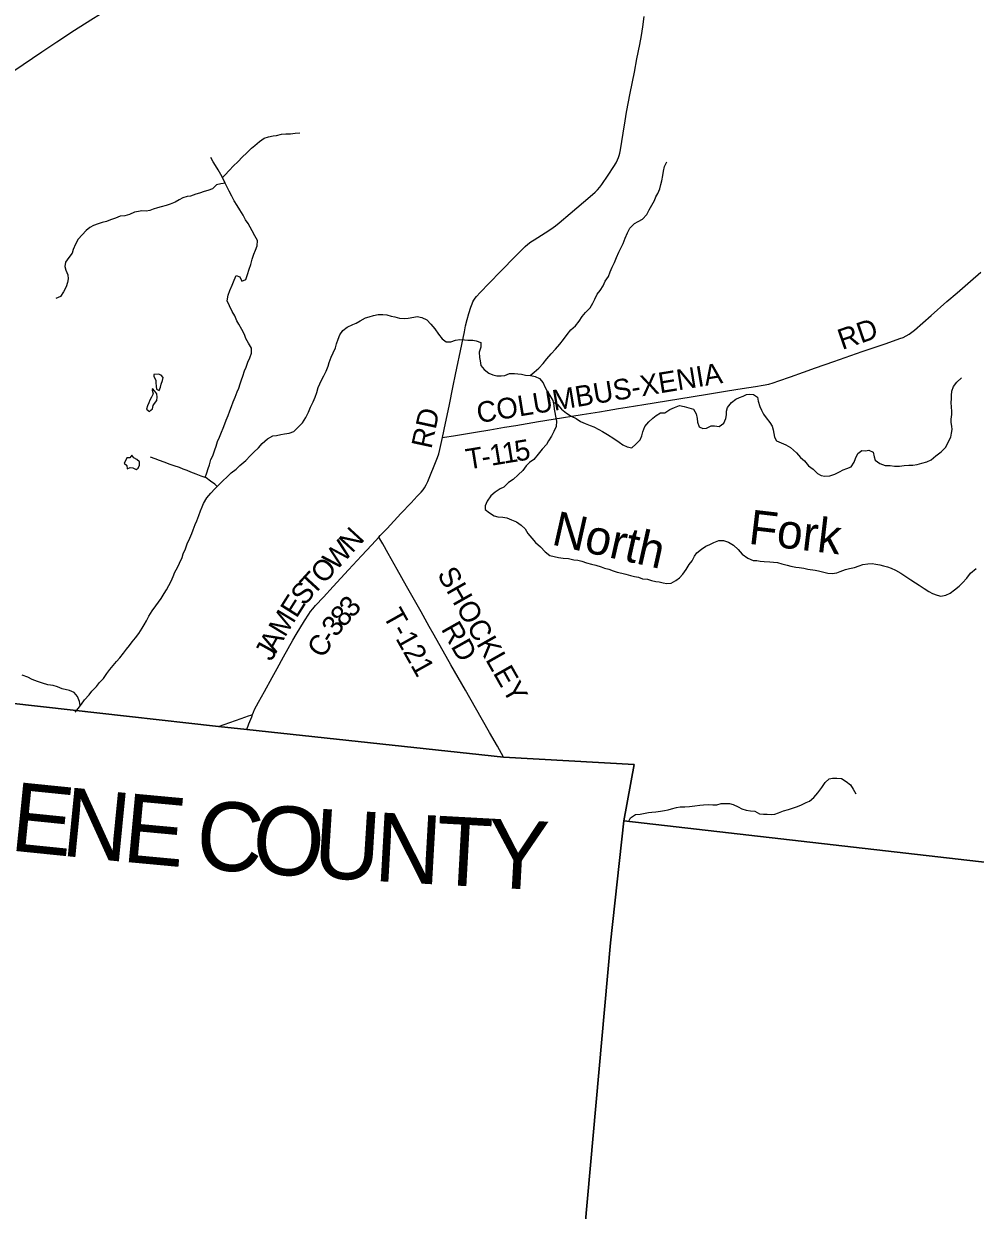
# Model space of a CAD drawing. Extents: x 1410790 to 1770854, y 566777 to 831614.
# Drawn here: x 1637179 to 1651013, y 642079 to 659329 of the extents above; entities that cross this region are included whole.
import ezdxf

# ---------------------------------------------------------------- set-up
doc = ezdxf.new("R2010")
doc.units = 0
for name, color, linetype in [('GM_X_Adjacent_County', 7, 'Continuous'), ('GM_X_Adjacent_County_Text', 7, 'Continuous'), ('GM_X_County', 7, 'Continuous'), ('GM_X_County_Road', 7, 'Continuous'), ('GM_X_County_Road_Text', 7, 'Continuous'), ('GM_X_Minor_Lake', 7, 'Continuous'), ('GM_X_Minor_River', 7, 'Continuous'), ('GM_X_Minor_River_Text', 7, 'Continuous'), ('GM_X_Township', 7, 'Continuous'), ('GM_X_Township_Road', 7, 'Continuous'), ('GM_X_Township_Road_Text', 7, 'Continuous')]:
    doc.layers.add(name, color=color, linetype=linetype)

msp = doc.modelspace()

# ---------------------------------------------------------------- linework, layer by layer
at = {"layer": 'GM_X_Adjacent_County'}
for points in [[(1671974, 683181), (1671693, 682151), (1669822, 675181), (1669783, 675026), (1667943, 667921), (1667581, 666498), (1666885, 663874), (1666084, 660564), (1663561, 650929), (1663296, 649933), (1662403, 645855), (1656287, 646528), (1652288, 647008), (1645905, 647740), (1645710, 645966), (1645124, 639449)], [(1645124, 639449), (1645710, 645966), (1645905, 647740), (1646054, 648559), (1644155, 648666), (1640422, 649068), (1640009, 649114), (1636122, 649546)]]:
    msp.add_lwpolyline(points, dxfattribs=at)
at = {"layer": 'GM_X_County'}
msp.add_lwpolyline([(1671974, 683181), (1671693, 682151), (1669822, 675181), (1669783, 675026), (1667943, 667921), (1667581, 666498), (1666885, 663874), (1666084, 660564), (1663561, 650929), (1663296, 649933), (1662403, 645855), (1656287, 646528), (1652288, 647008), (1645905, 647740), (1646054, 648559), (1644155, 648666), (1640422, 649068), (1640009, 649114), (1636122, 649546)], dxfattribs=at)
at = {"layer": 'GM_X_County_Road'}
for points in [[(1636750, 658448), (1636844, 658513), (1636979, 658605), (1637169, 658736), (1637441, 658919), (1637659, 659066), (1637919, 659237), (1638155, 659386), (1638294, 659472), (1638461, 659576), (1638767, 659768), (1638906, 659855), (1639087, 659968), (1639310, 660107), (1639478, 660210), (1639869, 660451), (1640134, 660615), (1640329, 660736), (1640524, 660857), (1640691, 660961), (1640872, 661072), (1641016, 661164)], [(1643266, 653314), (1643309, 653523), (1643363, 653771), (1643424, 654064), (1643458, 654228), (1643548, 654667), (1643585, 654850), (1643604, 654939), (1643627, 655027), (1643652, 655118), (1643679, 655208), (1643697, 655257), (1643709, 655284), (1643725, 655311), (1643742, 655338), (1643764, 655365), (1643817, 655423), (1643947, 655557), (1644116, 655733), (1644328, 655951), (1644424, 656047), (1644470, 656091), (1644509, 656124), (1644552, 656156), (1644602, 656189), (1644762, 656289), (1644844, 656343), (1644911, 656391), (1644962, 656432), (1645124, 656571), (1645412, 656815), (1645486, 656880), (1645521, 656915), (1645553, 656953), (1645583, 656993), (1645674, 657129), (1645756, 657252), (1645790, 657308), (1645813, 657352), (1645826, 657383), (1645837, 657414), (1645845, 657446), (1645855, 657495), (1645894, 657738), (1645923, 657916), (1645944, 658045), (1645996, 658319), (1646057, 658625), (1646094, 658818), (1646136, 659027), (1646160, 659156), (1646180, 659286), (1646199, 659433)], [(1642341, 651865), (1642363, 651888), (1642461, 651990), (1642661, 652207), (1642810, 652363), (1642901, 652459), (1642955, 652519), (1642986, 652555), (1643005, 652582), (1643030, 652625), (1643053, 652672), (1643084, 652747), (1643156, 652925), (1643194, 653025), (1643212, 653078), (1643228, 653140), (1643266, 653314)], [(1640506, 649287), (1640519, 649320), (1640536, 649359), (1640593, 649468), (1640679, 649622), (1640791, 649825), (1640863, 649954), (1640957, 650125), (1641092, 650366), (1641141, 650451), (1641261, 650647), (1641322, 650743), (1641350, 650784), (1641380, 650822), (1641423, 650872), (1641535, 650991), (1641680, 651148), (1641903, 651389), (1642092, 651594), (1642239, 651755), (1642341, 651865)], [(1640009, 649114), (1640340, 649229), (1640448, 649266), (1640480, 649278), (1640506, 649287)], [(1640422, 649068), (1640454, 649153), (1640493, 649255), (1640506, 649287)]]:
    msp.add_lwpolyline(points, dxfattribs=at)
at = {"layer": 'GM_X_Minor_Lake'}
for points in [[(1639157, 654021), (1639166, 654045), (1639176, 654091), (1639197, 654141), (1639205, 654185), (1639176, 654221), (1639136, 654235), (1639070, 654228)], [(1639070, 654228), (1639072, 654200), (1639101, 654148), (1639102, 654107), (1639104, 654059), (1639107, 654015), (1639147, 653997), (1639157, 654021)], [(1639051, 654024), (1639044, 654003), (1639059, 653950), (1639036, 653898), (1639014, 653858), (1638999, 653816), (1638977, 653772), (1638966, 653724), (1639008, 653692), (1639028, 653711)], [(1639028, 653711), (1639049, 653731), (1639063, 653777), (1639081, 653809), (1639112, 653853), (1639120, 653899), (1639113, 653947), (1639083, 653989), (1639051, 654024)], [(1638694, 653019), (1638679, 653020), (1638660, 652976), (1638640, 652942), (1638676, 652908), (1638685, 652856), (1638727, 652877), (1638767, 652871), (1638813, 652850)], [(1638813, 652850), (1638842, 652870), (1638864, 652910), (1638861, 652958), (1638825, 652996), (1638779, 653017), (1638753, 653057), (1638723, 653017), (1638694, 653019)]]:
    msp.add_lwpolyline(points, dxfattribs=at)
at = {"layer": 'GM_X_Minor_River'}
for points in [[(1640070, 657091), (1640109, 657131), (1640167, 657196), (1640230, 657262), (1640293, 657321), (1640358, 657393), (1640416, 657446), (1640489, 657518), (1640540, 657559), (1640605, 657617), (1640673, 657666), (1640740, 657685), (1640804, 657697), (1640854, 657704), (1640926, 657722), (1640991, 657727), (1641059, 657726), (1641127, 657738), (1641195, 657743)], [(1639816, 652732), (1639839, 652798), (1639860, 652862), (1639879, 652918), (1639901, 652992), (1639930, 653049), (1639957, 653135), (1639975, 653187), (1639998, 653253), (1640027, 653317), (1640054, 653389), (1640078, 653449), (1640103, 653512), (1640124, 653566), (1640152, 653634), (1640177, 653700), (1640200, 653764), (1640226, 653834), (1640251, 653898), (1640280, 653975), (1640305, 654031), (1640325, 654093), (1640346, 654153), (1640366, 654205), (1640389, 654285), (1640412, 654337), (1640435, 654407), (1640465, 654470), (1640490, 654538), (1640489, 654610), (1640447, 654683), (1640408, 654751), (1640388, 654812), (1640349, 654886), (1640308, 654961), (1640278, 655011), (1640247, 655080), (1640207, 655146), (1640170, 655229), (1640137, 655301), (1640151, 655381), (1640176, 655449), (1640209, 655527), (1640240, 655601), (1640267, 655670), (1640320, 655650), (1640352, 655585), (1640408, 655611), (1640431, 655685), (1640458, 655759), (1640481, 655831), (1640499, 655908), (1640524, 655980), (1640547, 656038), (1640572, 656102), (1640576, 656176), (1640539, 656243), (1640501, 656317), (1640472, 656370), (1640440, 656424), (1640401, 656479), (1640369, 656545), (1640320, 656622), (1640283, 656684), (1640239, 656753), (1640204, 656823), (1640164, 656894), (1640129, 656972), (1640105, 657022), (1640080, 657073), (1640044, 657139), (1640005, 657204), (1639968, 657268), (1639934, 657319), (1639899, 657385)], [(1644544, 654214), (1644601, 654261), (1644666, 654320), (1644731, 654390), (1644785, 654457), (1644848, 654531), (1644909, 654600), (1644972, 654668), (1645027, 654737), (1645078, 654809), (1645134, 654878), (1645201, 654936), (1645256, 655003), (1645299, 655073), (1645345, 655131), (1645412, 655200), (1645455, 655266), (1645480, 655326), (1645514, 655396), (1645559, 655453), (1645602, 655519), (1645631, 655587), (1645683, 655654), (1645706, 655722), (1645735, 655792), (1645768, 655856), (1645798, 655930), (1645831, 656007), (1645864, 656075), (1645895, 656133), (1645925, 656209), (1645956, 656289), (1645989, 656355), (1646058, 656424), (1646110, 656455), (1646177, 656489), (1646236, 656556), (1646270, 656622), (1646313, 656690), (1646348, 656758), (1646370, 656812), (1646399, 656863), (1646426, 656931), (1646444, 656993), (1646457, 657045), (1646472, 657121), (1646480, 657187), (1646493, 657255), (1646530, 657321)], [(1640112, 657009), (1640045, 657003), (1639983, 656986), (1639922, 656930), (1639854, 656903), (1639803, 656891), (1639735, 656866), (1639679, 656850), (1639606, 656823), (1639556, 656816), (1639492, 656796), (1639437, 656769), (1639381, 656737), (1639310, 656706), (1639248, 656688), (1639176, 656669), (1639125, 656654), (1639063, 656632), (1639013, 656613), (1638961, 656603), (1638897, 656610), (1638846, 656600), (1638788, 656589), (1638716, 656556), (1638651, 656538), (1638581, 656529), (1638513, 656504), (1638440, 656476), (1638382, 656455), (1638321, 656437), (1638261, 656422), (1638195, 656397), (1638138, 656367), (1638088, 656321), (1638027, 656260), (1637972, 656196), (1637931, 656125), (1637899, 656049), (1637882, 655995), (1637833, 655931), (1637788, 655862), (1637776, 655798), (1637789, 655747), (1637819, 655677), (1637826, 655621), (1637816, 655565), (1637795, 655503), (1637756, 655433), (1637715, 655364), (1637647, 655334)], [(1637927, 649320), (1637969, 649375), (1638018, 649439), (1638063, 649499), (1638128, 649574), (1638168, 649626), (1638235, 649693), (1638280, 649751), (1638340, 649812), (1638387, 649882), (1638430, 649942), (1638477, 649999), (1638529, 650055), (1638574, 650108), (1638629, 650176), (1638673, 650238), (1638716, 650291), (1638757, 650345), (1638805, 650401), (1638852, 650466), (1638901, 650540), (1638931, 650592), (1638962, 650649), (1638999, 650717), (1639048, 650793), (1639101, 650866), (1639178, 650974), (1639219, 651045), (1639257, 651099), (1639321, 651223), (1639351, 651294), (1639378, 651356), (1639415, 651424), (1639445, 651488), (1639482, 651570), (1639497, 651621), (1639532, 651695), (1639556, 651767), (1639595, 651851), (1639622, 651919), (1639643, 651973), (1639672, 652048), (1639694, 652104), (1639725, 652178), (1639750, 652248), (1639772, 652304), (1639793, 652356), (1639840, 652435), (1639899, 652503), (1639957, 652566), (1640012, 652622), (1640079, 652689), (1640133, 652737), (1640196, 652802), (1640269, 652854), (1640322, 652907), (1640406, 652981), (1640473, 653048), (1640522, 653100), (1640593, 653161), (1640647, 653224), (1640722, 653292), (1640799, 653337), (1640855, 653343), (1640919, 653358), (1640972, 653367), (1641038, 653377), (1641106, 653402), (1641171, 653464), (1641232, 653525), (1641279, 653603), (1641320, 653683), (1641350, 653756), (1641387, 653832), (1641414, 653900), (1641439, 653966), (1641461, 654040), (1641484, 654096), (1641509, 654147), (1641541, 654209), (1641576, 654279), (1641607, 654351), (1641621, 654405), (1641650, 654479), (1641677, 654544), (1641710, 654618), (1641728, 654674), (1641749, 654742), (1641774, 654806), (1641816, 654868), (1641883, 654919), (1641962, 654956), (1642014, 654978), (1642070, 655011), (1642147, 655051), (1642199, 655070), (1642264, 655089), (1642330, 655103), (1642400, 655102), (1642456, 655098), (1642522, 655077)], [(1642522, 655077), (1642572, 655066), (1642640, 655050), (1642714, 655043), (1642770, 655046), (1642849, 655064), (1642901, 655071), (1642969, 655056), (1643039, 655026), (1643096, 654963), (1643154, 654894), (1643211, 654818), (1643263, 654747), (1643322, 654704), (1643388, 654702), (1643455, 654727), (1643517, 654738), (1643585, 654734), (1643635, 654729), (1643707, 654728), (1643758, 654720), (1643823, 654697), (1643827, 654629), (1643802, 654555), (1643805, 654477), (1643815, 654427), (1643824, 654359), (1643872, 654304), (1643939, 654251), (1643997, 654225), (1644059, 654208), (1644121, 654209), (1644172, 654217), (1644242, 654244), (1644312, 654244), (1644362, 654237), (1644414, 654233), (1644474, 654222), (1644550, 654213), (1644616, 654201), (1644680, 654172), (1644730, 654107), (1644753, 654051), (1644787, 653986), (1644830, 653922), (1644870, 653849), (1644887, 653781), (1644892, 653727), (1644900, 653677), (1644912, 653623), (1644925, 653550), (1644922, 653474), (1644887, 653403), (1644851, 653335), (1644810, 653263), (1644777, 653211), (1644716, 653144), (1644657, 653072), (1644593, 652995), (1644532, 652951), (1644485, 652900), (1644433, 652832), (1644366, 652769), (1644295, 652701), (1644228, 652658), (1644158, 652593), (1644107, 652567), (1644035, 652518), (1643968, 652464), (1643915, 652389), (1643886, 652319), (1643888, 652269), (1643951, 652218), (1644019, 652175), (1644073, 652161), (1644143, 652154), (1644201, 652145), (1644271, 652117), (1644341, 652088), (1644413, 652041), (1644468, 651987), (1644510, 651916), (1644567, 651851), (1644619, 651789), (1644690, 651726), (1644762, 651651), (1644827, 651598), (1644891, 651582), (1644953, 651567), (1645020, 651560), (1645100, 651552), (1645176, 651537), (1645234, 651530), (1645294, 651516), (1645360, 651493), (1645434, 651472), (1645498, 651456), (1645572, 651435), (1645624, 651416), (1645685, 651398), (1645749, 651375)], [(1650105, 652912), (1650169, 652922), (1650237, 652939), (1650308, 652958), (1650374, 652990), (1650439, 653047), (1650516, 653106), (1650583, 653172), (1650619, 653248), (1650656, 653317), (1650669, 653375), (1650679, 653429), (1650674, 653480), (1650662, 653530), (1650663, 653582), (1650671, 653646), (1650672, 653696), (1650669, 653754), (1650665, 653820), (1650666, 653874), (1650666, 653924), (1650673, 653988), (1650696, 654056), (1650746, 654120), (1650811, 654179)], [(1644876, 653826), (1644939, 653791), (1644997, 653726), (1645068, 653669), (1645138, 653626), (1645212, 653592), (1645274, 653547), (1645340, 653518), (1645413, 653489), (1645467, 653469), (1645541, 653432), (1645595, 653402), (1645665, 653359), (1645756, 653300), (1645834, 653245), (1645888, 653208), (1645950, 653178), (1646018, 653161), (1646080, 653218), (1646139, 653282), (1646164, 653338), (1646180, 653398), (1646211, 653474), (1646266, 653543), (1646325, 653597), (1646375, 653632), (1646436, 653670), (1646502, 653671), (1646574, 653720), (1646639, 653748), (1646713, 653777), (1646783, 653764), (1646847, 653744), (1646915, 653723), (1646955, 653656), (1646972, 653590), (1646976, 653538), (1647001, 653470), (1647053, 653445), (1647105, 653451), (1647174, 653482), (1647224, 653482), (1647290, 653475), (1647358, 653524), (1647385, 653590), (1647394, 653644), (1647396, 653694), (1647409, 653752), (1647468, 653820), (1647530, 653871), (1647585, 653897), (1647637, 653916), (1647687, 653938), (1647737, 653945), (1647789, 653941), (1647847, 653898), (1647859, 653840), (1647882, 653764), (1647906, 653713), (1647935, 653653), (1647973, 653598), (1648028, 653534), (1648062, 653479), (1648077, 653425), (1648085, 653373), (1648094, 653317), (1648122, 653266), (1648189, 653234), (1648261, 653209), (1648325, 653166), (1648413, 653089), (1648472, 653025), (1648528, 652976), (1648587, 652903), (1648655, 652852), (1648718, 652790), (1648772, 652761), (1648826, 652749), (1648898, 652756), (1648973, 652779), (1649041, 652813), (1649094, 652842), (1649144, 652864), (1649209, 652889), (1649251, 652953), (1649272, 653009), (1649305, 653082), (1649363, 653126), (1649415, 653121), (1649468, 653129), (1649529, 653102), (1649543, 653034), (1649556, 652982), (1649624, 652937), (1649704, 652906), (1649774, 652906), (1649840, 652899), (1649910, 652896), (1649981, 652907), (1650047, 652911), (1650105, 652912)], [(1639993, 652603), (1639956, 652636), (1639892, 652679), (1639829, 652728), (1639759, 652749), (1639685, 652779), (1639609, 652808), (1639553, 652835), (1639497, 652855), (1639443, 652876), (1639367, 652903), (1639309, 652919), (1639223, 652954), (1639155, 652977), (1639092, 653004), (1639020, 653028)], [(1645749, 651375), (1645809, 651356), (1645875, 651340), (1645931, 651325), (1646001, 651308), (1646059, 651294), (1646117, 651283), (1646173, 651259), (1646249, 651252), (1646305, 651235), (1646369, 651221), (1646419, 651214), (1646475, 651202), (1646527, 651193), (1646592, 651194), (1646658, 651234), (1646715, 651271), (1646763, 651329), (1646810, 651393), (1646853, 651466), (1646898, 651520), (1646932, 651588), (1646967, 651639), (1647032, 651689), (1647098, 651732), (1647153, 651760), (1647213, 651787), (1647285, 651814), (1647354, 651816), (1647426, 651793), (1647497, 651750), (1647565, 651684), (1647622, 651615), (1647708, 651558), (1647784, 651527), (1647836, 651523), (1647888, 651514), (1647946, 651509), (1648026, 651505), (1648080, 651502), (1648136, 651494), (1648202, 651477), (1648276, 651458), (1648334, 651444), (1648402, 651429), (1648454, 651422), (1648522, 651412), (1648580, 651401), (1648685, 651384), (1648735, 651376), (1648793, 651359), (1648869, 651342), (1648931, 651334), (1648999, 651347), (1649049, 651364), (1649124, 651394), (1649184, 651407), (1649256, 651422), (1649327, 651450), (1649379, 651465), (1649449, 651479), (1649515, 651482), (1649567, 651473), (1649626, 651461), (1649678, 651448), (1649735, 651432), (1649791, 651415), (1649851, 651387), (1649929, 651342), (1650003, 651295), (1650074, 651246), (1650144, 651199), (1650196, 651167), (1650270, 651118), (1650337, 651075), (1650391, 651047), (1650457, 651022), (1650511, 651009), (1650586, 651023), (1650648, 651052), (1650709, 651098), (1650779, 651151), (1650826, 651203), (1650889, 651268), (1650945, 651342), (1651028, 651411)], [(1638000, 649415), (1637992, 649477), (1637961, 649546), (1637911, 649606), (1637843, 649635), (1637739, 649660), (1637670, 649691), (1637606, 649706), (1637530, 649720), (1637452, 649741), (1637378, 649764), (1637304, 649797), (1637238, 649831), (1637156, 649856)], [(1645977, 647734), (1646003, 647785), (1646071, 647831), (1646142, 647836), (1646192, 647848), (1646262, 647861), (1646312, 647868), (1646367, 647872), (1646435, 647881), (1646495, 647891), (1646549, 647902), (1646599, 647914), (1646668, 647933), (1646724, 647942), (1646792, 647944), (1646856, 647951), (1646935, 647958), (1647007, 647968), (1647063, 647975), (1647135, 647980), (1647197, 647972), (1647254, 647975), (1647320, 647991), (1647376, 647992), (1647442, 647995), (1647494, 647979), (1647566, 647944), (1647620, 647914), (1647682, 647897), (1647746, 647886), (1647806, 647880), (1647878, 647843), (1647934, 647838), (1647988, 647838), (1648046, 647835), (1648098, 647839), (1648151, 647858), (1648223, 647886), (1648299, 647907), (1648354, 647924), (1648430, 647950), (1648489, 647973), (1648555, 648008), (1648605, 648028), (1648668, 648079), (1648725, 648147), (1648780, 648225), (1648831, 648298), (1648889, 648350), (1648939, 648359), (1649002, 648361), (1649068, 648356), (1649137, 648311), (1649199, 648264), (1649237, 648202), (1649276, 648134)]]:
    msp.add_lwpolyline(points, dxfattribs=at)
at = {"layer": 'GM_X_Township'}
msp.add_lwpolyline([(1636122, 649546), (1640009, 649114), (1640422, 649068), (1644155, 648666), (1646054, 648559), (1645905, 647740), (1652288, 647008), (1656287, 646528), (1662403, 645855), (1663296, 649933), (1663561, 650929), (1666084, 660564), (1666885, 663874), (1667581, 666498), (1667943, 667921), (1669783, 675026), (1669822, 675181), (1659011, 676224), (1657686, 676331), (1656836, 676404), (1649879, 677009), (1644674, 677520), (1639318, 678094), (1633970, 678678)], dxfattribs=at)
at = {"layer": 'GM_X_Township_Road'}
for points in [[(1643266, 653314), (1643298, 653319), (1643426, 653339), (1643746, 653391), (1643954, 653426), (1644170, 653462), (1644335, 653488), (1644416, 653501), (1644665, 653544), (1644877, 653581), (1645299, 653649), (1645549, 653688), (1645662, 653707), (1645824, 653734), (1645954, 653753), (1646194, 653793), (1646705, 653877), (1647120, 653944), (1647411, 653991), (1647622, 654024), (1647816, 654055), (1647930, 654074), (1648010, 654090), (1648074, 654108), (1648159, 654136), (1648326, 654195), (1648517, 654263), (1648692, 654327), (1648959, 654420), (1649370, 654562), (1649716, 654681), (1649918, 654751), (1649964, 654769), (1650009, 654791), (1650051, 654816), (1650092, 654845), (1650130, 654876), (1650373, 655088), (1650599, 655289), (1650748, 655419), (1650946, 655588), (1651095, 655717)], [(1644155, 648666), (1644065, 648826), (1643950, 649025), (1643747, 649382), (1643600, 649638), (1643390, 650010), (1643148, 650438), (1643074, 650566), (1642955, 650781), (1642746, 651154), (1642608, 651396), (1642479, 651625), (1642398, 651768), (1642357, 651838), (1642341, 651865)]]:
    msp.add_lwpolyline(points, dxfattribs=at)

# ---------------------------------------------------------------- texts
at = {"layer": 'GM_X_Adjacent_County_Text'}
for s, rotation, p in [('E', 354.2037, (1636963, 647312)), ('N', 354.3532, (1637710, 647236)), ('E', 354.6905, (1638597, 647149)), ('C', 355.4795, (1639659, 647052)), ('O', 355.809, (1640477, 646988)), ('U', 356.4617, (1641371, 646922)), ('N', 356.7801, (1642260, 646867)), ('T', 356.8584, (1643145, 646817)), ('Y', 356.8626, (1643892, 646776))]:
    msp.add_text(s, height=1000, rotation=rotation, dxfattribs=at).set_placement(p)
at = {"layer": 'GM_X_County_Road_Text'}
for s, rotation, p in [('RD', 77.7169, (1643105, 653138)), ('N', 47.4465, (1641954, 651621)), ('W', 47.4451, (1641719, 651365)), ('O', 47.4452, (1641541, 651171)), ('T', 47.4706, (1641389, 651005)), ('S', 48.7926, (1641257, 650854)), ('E', 57.6591, (1641144, 650675)), ('8', 47.6356, (1641830, 650541)), ('3', 47.6062, (1641955, 650678)), ('M', 58.7346, (1640976, 650398)), ('3', 53.2082, (1641724, 650399)), ('J', 61.0532, (1640780, 650047)), ('A', 60.6008, (1640848, 650170)), ('C', 58.6888, (1641536, 650090)), ('-', 58.1982, (1641663, 650300))]:
    msp.add_text(s, height=300, rotation=rotation, dxfattribs=at).set_placement(p)
at = {"layer": 'GM_X_Minor_River_Text'}
for s, rotation, p in [('North', 347.3325, (1644838, 651761)), ('Fork', 353.2773, (1647704, 651770))]:
    msp.add_text(s, height=500, rotation=rotation, dxfattribs=at).set_placement(p)
at = {"layer": 'GM_X_Township_Road_Text'}
for s, rotation, p in [('RD', 19.0576, (1649077, 654585)), ('COLUMBUS-XENIA', 9.3381, (1643790, 653521)), ('5', 9.4623, (1644342, 652962)), ('T', 9.2263, (1643633, 652846)), ('1', 9.2401, (1643976, 652902)), ('1', 9.2632, (1644159, 652932)), ('-', 9.2236, (1643855, 652882)), ('SHOCKLEY', 299.5051, (1643183, 651327)), ('T-121', 299.1908, (1642394, 650725)), ('RD', 299.4382, (1643240, 650530))]:
    msp.add_text(s, height=300, rotation=rotation, dxfattribs=at).set_placement(p)

doc.saveas('drawing.dxf')
